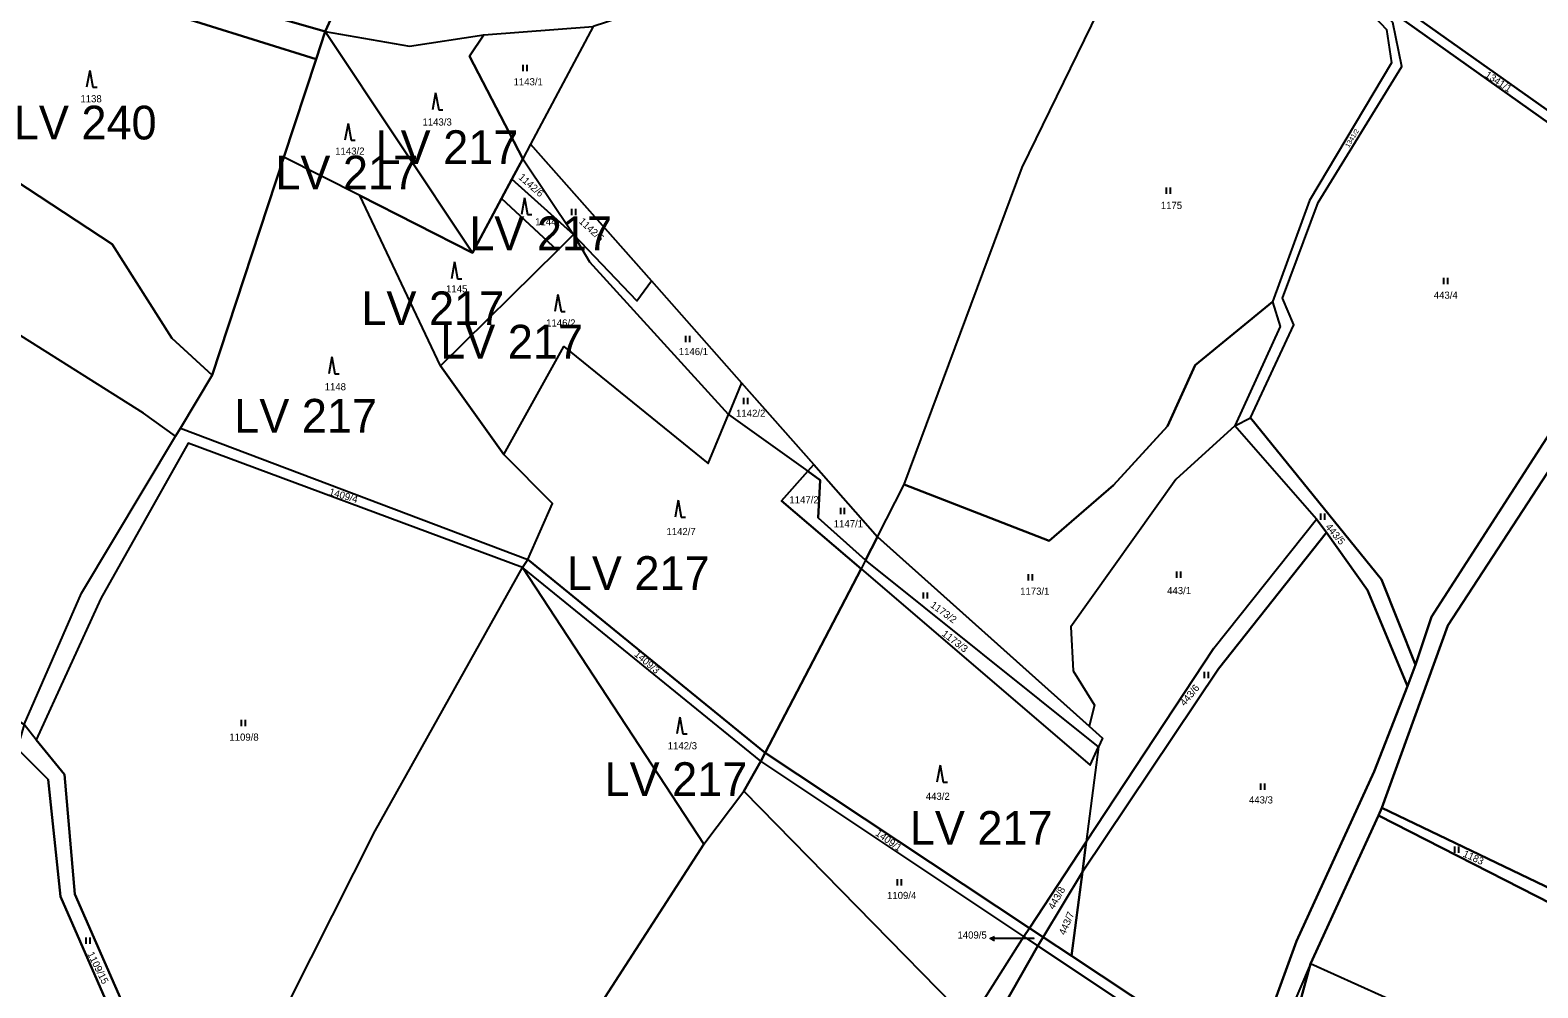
# Model space of a CAD drawing. Extents: x -588699 to -585793, y -1060280 to -1056731.
# Drawn here: x -587487.8 to -587129.7, y -1059020.2 to -1058792.9 of the extents above; entities that cross this region are included whole.
import ezdxf

# ---------------------------------------------------------------- set-up
doc = ezdxf.new("R2010")
doc.units = 0
for name, color, linetype in [('Druh pozemku', 7, 'Continuous'), ('Parcela nároku', 7, 'Continuous'), ('Parcelní číslo', 7, 'Continuous'), ('Vnější obvod_převzatý', 7, 'Continuous')]:
    doc.layers.add(name, color=color, linetype=linetype)

msp = doc.modelspace()

# ---------------------------------------------------------------- linework, layer by layer
at = {"layer": 'Druh pozemku'}
for p, q in [((-587473.6, -1058802.43), (-587474.33, -1058806.43)), ((-587473.6, -1058802.43), (-587472.87, -1058806.43)), ((-587370.75, -1058801.12), (-587370.75, -1058802.62)), ((-587369.72, -1058802.62), (-587369.72, -1058801.12)), ((-587472.87, -1058806.43), (-587471.87, -1058806.43)), ((-587391.46, -1058807.75), (-587392.2, -1058811.75)), ((-587391.46, -1058807.75), (-587390.73, -1058811.75)), ((-587390.73, -1058811.75), (-587389.73, -1058811.75)), ((-587412.26, -1058815), (-587412.99, -1058819)), ((-587412.26, -1058815), (-587411.53, -1058819)), ((-587411.53, -1058819), (-587410.53, -1058819)), ((-587218.02, -1058830.22), (-587218.02, -1058831.72)), ((-587216.99, -1058831.72), (-587216.99, -1058830.22)), ((-587370.36, -1058832.66), (-587371.09, -1058836.66)), ((-587370.36, -1058832.66), (-587369.63, -1058836.66)), ((-587359.2, -1058835.32), (-587359.2, -1058836.82)), ((-587358.18, -1058836.82), (-587358.18, -1058835.32)), ((-587369.63, -1058836.66), (-587368.63, -1058836.66)), ((-587386.97, -1058847.89), (-587387.7, -1058851.89)), ((-587386.97, -1058847.89), (-587386.24, -1058851.89)), ((-587386.24, -1058851.89), (-587385.24, -1058851.89)), ((-587152.12, -1058851.67), (-587152.12, -1058853.17)), ((-587151.09, -1058853.17), (-587151.09, -1058851.67)), ((-587362.41, -1058855.65), (-587363.15, -1058859.65)), ((-587362.41, -1058855.65), (-587361.68, -1058859.65)), ((-587361.68, -1058859.65), (-587360.68, -1058859.65)), ((-587332.14, -1058865.4), (-587332.14, -1058866.9)), ((-587331.11, -1058866.9), (-587331.11, -1058865.4)), ((-587416.11, -1058870.44), (-587416.84, -1058874.44)), ((-587416.11, -1058870.44), (-587415.38, -1058874.44)), ((-587415.38, -1058874.44), (-587414.38, -1058874.44)), ((-587318.39, -1058880.11), (-587318.39, -1058881.61)), ((-587317.36, -1058881.61), (-587317.36, -1058880.11)), ((-587333.88, -1058904.43), (-587334.61, -1058908.43)), ((-587333.88, -1058904.43), (-587333.15, -1058908.43)), ((-587295.35, -1058906.29), (-587295.35, -1058907.79)), ((-587294.33, -1058907.79), (-587294.33, -1058906.29)), ((-587333.15, -1058908.43), (-587332.15, -1058908.43)), ((-587181.3, -1058907.6), (-587181.3, -1058909.1)), ((-587180.28, -1058909.1), (-587180.28, -1058907.6)), ((-587250.74, -1058921.98), (-587250.74, -1058923.48)), ((-587249.71, -1058923.48), (-587249.71, -1058921.98)), ((-587215.49, -1058921.4), (-587215.49, -1058922.9)), ((-587214.46, -1058922.9), (-587214.46, -1058921.4)), ((-587275.66, -1058926.31), (-587275.66, -1058927.81)), ((-587274.64, -1058927.81), (-587274.64, -1058926.31)), ((-587208.94, -1058945.18), (-587208.94, -1058946.68)), ((-587207.92, -1058946.68), (-587207.92, -1058945.18)), ((-587437.66, -1058956.56), (-587437.66, -1058958.06)), ((-587436.64, -1058958.06), (-587436.64, -1058956.56)), ((-587333.48, -1058955.93), (-587334.21, -1058959.93)), ((-587333.48, -1058955.93), (-587332.75, -1058959.93)), ((-587332.75, -1058959.93), (-587331.75, -1058959.93)), ((-587271.67, -1058967.33), (-587272.41, -1058971.33)), ((-587271.67, -1058967.33), (-587270.94, -1058971.33)), ((-587270.94, -1058971.33), (-587269.94, -1058971.33)), ((-587195.58, -1058971.66), (-587195.58, -1058973.16)), ((-587194.56, -1058973.16), (-587194.56, -1058971.66)), ((-587149.51, -1058986.6), (-587149.51, -1058988.1)), ((-587148.48, -1058988.1), (-587148.48, -1058986.6)), ((-587281.85, -1058994.38), (-587281.85, -1058995.88)), ((-587280.83, -1058995.88), (-587280.83, -1058994.38)), ((-587474.54, -1059008.25), (-587474.54, -1059009.75)), ((-587473.52, -1059009.75), (-587473.52, -1059008.25))]:
    msp.add_line(p, q, dxfattribs=at)
at = {"layer": 'Parcela nároku'}
for points in [[(-587095.97, -1058834.07), (-587178.54, -1058775.59), (-587199.34, -1058768.09), (-587207.44, -1058733.83), (-587185.32, -1058687.57), (-587182.12, -1058689.03), (-587133.66, -1058696.26), (-587132.92, -1058684.88), (-587132.73, -1058682.03), (-587134.03, -1058665.11), (-587141.42, -1058647.46), (-587163.08, -1058643.05), (-587163.66, -1058639.96), (-587161.65, -1058627.33), (-587140.01, -1058634.05), (-587129.38, -1058630.44)], [(-587416.34, -1058790.27), (-587417.7, -1058793.2), (-587397.65, -1058796.7), (-587380.04, -1058794), (-587354.02, -1058791.99)], [(-587198.44, -1059040.46), (-587187.03, -1059009.07), (-587168.6, -1058968.87), (-587160.7, -1058948.56), (-587158.75, -1058943.55), (-587154.97, -1058932.12), (-587114.84, -1058869.89)], [(-587112.04, -1058874.39), (-587151.08, -1058934.21), (-587166.73, -1058977.44), (-587167.55, -1058979.24), (-587183.73, -1059014.5), (-587223.98, -1059108.89)]]:
    msp.add_lwpolyline(points, dxfattribs=at)
for points in [[(-587330.16, -1058779.5), (-587337.53, -1058786.61), (-587354.02, -1058791.99), (-587368.94, -1058819.94), (-587340.22, -1058852.41), (-587318.82, -1058876.59), (-587301.68, -1058895.97), (-587286.5, -1058913.13), (-587280.18, -1058900.72), (-587252.21, -1058825.49), (-587209.44, -1058737.86), (-587213.81, -1058720.6), (-587228.19, -1058686.62), (-587279.6, -1058678.24), (-587283.54, -1058683.14), (-587295.15, -1058721.3), (-587317.99, -1058756.82)], [(-587252.21, -1058825.49), (-587209.44, -1058737.86), (-587202.09, -1058770.02), (-587180.64, -1058776.9), (-587165.69, -1058792.7), (-587164.49, -1058800.66), (-587183.93, -1058833.32), (-587192.75, -1058857.34), (-587211.09, -1058872.41), (-587217.64, -1058886.83), (-587230.5, -1058900.89), (-587245.79, -1058914.12), (-587280.18, -1058900.72)], [(-587498.02, -1058773.26), (-587471.36, -1058772.88), (-587419.8, -1058789.18), (-587416.34, -1058790.27), (-587417.7, -1058793.2), (-587474.82, -1058776.74), (-587499.41, -1058777.39), (-587534.25, -1058785.03), (-587576.88, -1058810.62), (-587586.16, -1058816.34), (-587588.18, -1058814.68), (-587546.21, -1058786.56), (-587534.66, -1058781.41)], [(-587474.82, -1058776.74), (-587417.7, -1058793.2), (-587419.85, -1058799.73), (-587474.59, -1058782.55), (-587495.05, -1058781.41), (-587500.85, -1058781.64), (-587499.41, -1058777.39)], [(-587187.67, -1058862.81), (-587190.34, -1058856.52), (-587181.86, -1058833.77), (-587161.98, -1058801.53), (-587164.12, -1058791.02), (-587171.29, -1058783.54), (-587180.64, -1058776.9), (-587165.69, -1058792.7), (-587164.49, -1058800.66), (-587183.93, -1058833.32), (-587192.75, -1058857.34), (-587190.91, -1058863.2), (-587201.67, -1058886.81), (-587197.97, -1058884.91)], [(-587178.54, -1058775.59), (-587095.97, -1058834.07), (-587097.12, -1058836.2), (-587171.29, -1058783.54)], [(-587500.85, -1058781.64), (-587495.05, -1058781.41), (-587474.59, -1058782.55), (-587419.85, -1058799.73), (-587427.49, -1058822.99), (-587444.5, -1058874.75), (-587454.12, -1058865.97), (-587468.24, -1058843.69), (-587508.54, -1058817.27), (-587512.1, -1058815), (-587519.56, -1058810.2), (-587511.16, -1058782.05)], [(-587181.86, -1058833.77), (-587161.98, -1058801.53), (-587164.12, -1058791.02), (-587171.29, -1058783.54), (-587097.12, -1058836.2), (-587114.84, -1058869.89), (-587154.97, -1058932.12), (-587158.75, -1058943.55), (-587166.85, -1058923.26), (-587197.97, -1058884.91), (-587187.67, -1058862.81), (-587190.34, -1058856.52)], [(-587380.04, -1058794), (-587354.02, -1058791.99), (-587368.94, -1058819.94), (-587370.78, -1058823.39), (-587383.42, -1058799.04)], [(-587419.85, -1058799.73), (-587417.7, -1058793.2), (-587382.71, -1058845.74), (-587409.49, -1058832.13), (-587427.49, -1058822.99)], [(-587397.65, -1058796.7), (-587380.04, -1058794), (-587383.42, -1058799.04), (-587370.78, -1058823.39), (-587373.37, -1058828.25), (-587375.82, -1058832.84), (-587382.71, -1058845.74), (-587417.7, -1058793.2)], [(-587534.2, -1058801.97), (-587529.95, -1058803.18), (-587524.77, -1058814), (-587519.56, -1058810.2), (-587512.1, -1058815), (-587508.54, -1058817.27), (-587468.24, -1058843.69), (-587454.12, -1058865.97), (-587444.5, -1058874.75), (-587452.08, -1058887.38), (-587453.2, -1058889.25), (-587460.84, -1058883.78), (-587522.15, -1058845.16), (-587576.88, -1058810.62), (-587549.72, -1058797.54)], [(-587151.08, -1058934.21), (-587112.04, -1058874.39), (-587094.24, -1058884.94), (-587054.26, -1058810.56), (-587030.43, -1058823.41), (-587014.91, -1058836.17), (-587018.01, -1058859.21), (-587024.71, -1058873.71), (-587054.07, -1058916.3), (-587105.47, -1058969.38), (-587107.83, -1058978.95), (-587124.19, -1058997.85), (-587166.73, -1058977.44)], [(-587340.22, -1058852.41), (-587368.94, -1058819.94), (-587370.78, -1058823.39), (-587358.71, -1058841.41), (-587343.66, -1058857.1)], [(-587390.34, -1058872.54), (-587409.49, -1058832.13), (-587427.49, -1058822.99), (-587444.5, -1058874.75), (-587452.08, -1058887.38), (-587369.55, -1058918.49), (-587363.73, -1058905.23), (-587375.25, -1058893.58)], [(-587373.37, -1058828.25), (-587370.78, -1058823.39), (-587358.71, -1058841.41)], [(-587375.82, -1058832.84), (-587373.37, -1058828.25), (-587358.71, -1058841.41), (-587362.51, -1058845.15)], [(-587375.82, -1058832.84), (-587362.51, -1058845.15), (-587390.34, -1058872.54), (-587409.49, -1058832.13), (-587382.71, -1058845.74)], [(-587354.84, -1058847.98), (-587358.71, -1058841.41), (-587362.51, -1058845.15), (-587390.34, -1058872.54), (-587375.25, -1058893.58), (-587361, -1058867.92), (-587326.78, -1058895.73), (-587321.93, -1058884.06)], [(-587358.71, -1058841.41), (-587343.66, -1058857.1), (-587340.22, -1058852.41), (-587318.82, -1058876.59), (-587321.93, -1058884.06), (-587354.84, -1058847.98)], [(-587522.15, -1058845.16), (-587543.94, -1058911.31), (-587530.26, -1058930.8), (-587489.18, -1058957.68), (-587475.53, -1058926.48), (-587453.2, -1058889.25), (-587460.84, -1058883.78)], [(-587240.62, -1058934.52), (-587240.05, -1058944.97), (-587235.03, -1058953.09), (-587236.26, -1058958.05), (-587286.5, -1058913.13), (-587280.18, -1058900.72), (-587245.79, -1058914.12), (-587230.5, -1058900.89), (-587217.64, -1058886.83), (-587211.09, -1058872.41), (-587192.75, -1058857.34), (-587190.91, -1058863.2), (-587201.67, -1058886.81), (-587215.69, -1058899.54)], [(-587326.78, -1058895.73), (-587321.93, -1058884.06), (-587303.11, -1058897.58), (-587309.31, -1058904.57), (-587290.42, -1058920.75), (-587313.22, -1058964.38), (-587369.55, -1058918.49), (-587363.73, -1058905.23), (-587375.25, -1058893.58), (-587361, -1058867.92)], [(-587301.68, -1058895.97), (-587318.82, -1058876.59), (-587321.93, -1058884.06), (-587303.11, -1058897.58)], [(-587197.97, -1058884.91), (-587166.85, -1058923.26), (-587158.75, -1058943.55), (-587160.7, -1058948.56), (-587170.21, -1058925.83), (-587179.94, -1058912.09), (-587182.28, -1058908.96), (-587201.67, -1058886.81)], [(-587489.18, -1058957.68), (-587475.53, -1058926.48), (-587453.2, -1058889.25), (-587452.08, -1058887.38), (-587369.55, -1058918.49), (-587370.84, -1058920.39), (-587450.19, -1058890.89), (-587470.98, -1058927.74), (-587486.32, -1058961.34)], [(-587201.67, -1058886.81), (-587215.69, -1058899.54), (-587240.62, -1058934.52), (-587240.05, -1058944.97), (-587235.03, -1058953.09), (-587236.26, -1058958.05), (-587233.09, -1058960.89), (-587234.03, -1058962.97), (-587236.95, -1058985.52), (-587206.63, -1058939.58), (-587182.28, -1058908.96)], [(-587470.98, -1058927.74), (-587486.32, -1058961.34), (-587479.58, -1058969.58), (-587477.12, -1058997.98), (-587465.03, -1059025.53), (-587462.84, -1059036.38), (-587445.39, -1059076.03), (-587426.09, -1059023.1), (-587405.83, -1058982.93), (-587370.84, -1058920.39), (-587450.19, -1058890.89)], [(-587303.11, -1058897.58), (-587301.68, -1058895.97), (-587286.5, -1058913.13), (-587289.35, -1058918.66), (-587300.64, -1058908.61), (-587300.16, -1058899.7)], [(-587309.31, -1058904.57), (-587303.11, -1058897.58), (-587300.16, -1058899.7), (-587300.64, -1058908.61), (-587289.35, -1058918.66), (-587290.42, -1058920.75)], [(-587206.63, -1058939.58), (-587182.28, -1058908.96), (-587179.94, -1058912.09), (-587205.52, -1058944.5), (-587237.88, -1058992.68), (-587236.95, -1058985.52)], [(-587289.35, -1058918.66), (-587286.5, -1058913.13), (-587236.26, -1058958.05), (-587233.09, -1058960.89), (-587234.03, -1058962.97)], [(-587205.52, -1058944.5), (-587179.94, -1058912.09), (-587170.21, -1058925.83), (-587160.7, -1058948.56), (-587168.6, -1058968.87), (-587187.03, -1059009.07), (-587198.44, -1059040.46), (-587240.46, -1059012.61), (-587237.88, -1058992.68)], [(-587472.64, -1059160.39), (-587420.19, -1059028.43), (-587426.09, -1059023.1), (-587405.83, -1058982.93), (-587370.84, -1058920.39), (-587327.75, -1058986.1), (-587352, -1059023.57), (-587374.2, -1059062.49), (-587384.36, -1059094.45), (-587392.6, -1059142.78), (-587403.28, -1059136.63), (-587416.21, -1059132.26), (-587431.57, -1059132.26), (-587446.44, -1059137.12), (-587462.61, -1059149.09)], [(-587370.84, -1058920.39), (-587369.55, -1058918.49), (-587313.22, -1058964.38), (-587314.26, -1058966.37)], [(-587314.26, -1058966.37), (-587370.84, -1058920.39), (-587327.75, -1058986.1), (-587318.3, -1058973.51)], [(-587313.22, -1058964.38), (-587290.42, -1058920.75), (-587236, -1058967.34), (-587234.03, -1058962.97), (-587236.95, -1058985.52), (-587250.46, -1059005.98)], [(-587234.03, -1058962.97), (-587289.35, -1058918.66), (-587290.42, -1058920.75), (-587236, -1058967.34)], [(-587479.58, -1058969.58), (-587486.32, -1058961.34), (-587489.18, -1058957.68), (-587490.84, -1058963.37), (-587483.48, -1058970.73), (-587480.52, -1058998.52), (-587467.05, -1059029.25), (-587466.55, -1059035.93), (-587447.41, -1059081.29), (-587445.39, -1059076.03), (-587462.84, -1059036.38), (-587465.03, -1059025.53), (-587477.12, -1058997.98)], [(-587507.67, -1059010.75), (-587518.99, -1059041.82), (-587509.34, -1059046.17), (-587512.35, -1059055.56), (-587522.91, -1059052.02), (-587539.49, -1059095.18), (-587562.32, -1059174.45), (-587544.58, -1059180.95), (-587489.61, -1059179.49), (-587482.72, -1059171.73), (-587447.41, -1059081.29), (-587466.55, -1059035.93), (-587467.05, -1059029.25), (-587480.52, -1058998.52), (-587483.48, -1058970.73), (-587490.84, -1058963.37)], [(-587314.26, -1058966.37), (-587318.3, -1058973.51), (-587264.6, -1059028.24), (-587251.79, -1059007.99)], [(-587313.22, -1058964.38), (-587250.46, -1059005.98), (-587251.79, -1059007.99), (-587314.26, -1058966.37)], [(-587352, -1059023.57), (-587327.75, -1058986.1), (-587318.3, -1058973.51), (-587264.6, -1059028.24), (-587323.79, -1059134.74), (-587339.95, -1059180.25), (-587392.6, -1059142.78), (-587384.36, -1059094.45), (-587374.2, -1059062.49)], [(-587167.55, -1058979.24), (-587166.73, -1058977.44), (-587124.19, -1058997.85), (-587126.31, -1059000.3)], [(-587178.21, -1059042.85), (-587173.18, -1059040.84), (-587161.23, -1059024.64), (-587183.73, -1059014.5), (-587167.55, -1058979.24), (-587126.31, -1059000.3), (-587104.24, -1059012.16), (-587128.43, -1059090.29), (-587155.26, -1059188.4), (-587209.63, -1059156.73), (-587230.3, -1059139), (-587220.32, -1059110.26), (-587212, -1059090.39), (-587190.48, -1059039.37)], [(-587250.46, -1059005.98), (-587236.95, -1058985.52), (-587237.88, -1058992.68), (-587247.23, -1059008.12)], [(-587247.23, -1059008.12), (-587237.88, -1058992.68), (-587240.46, -1059012.61)], [(-587251.79, -1059007.99), (-587250.46, -1059005.98), (-587247.23, -1059008.12), (-587248.47, -1059010.2)], [(-587339.95, -1059180.25), (-587323.79, -1059134.74), (-587264.6, -1059028.24), (-587251.79, -1059007.99), (-587248.47, -1059010.2), (-587300.25, -1059101.27), (-587302.6, -1059105.17), (-587320.05, -1059135.74), (-587337.12, -1059182.26)], [(-587248.47, -1059010.2), (-587199.45, -1059042.86), (-587227.19, -1059109.85), (-587235.69, -1059139.11), (-587239.06, -1059150.72), (-587300.25, -1059101.27)], [(-587248.47, -1059010.2), (-587247.23, -1059008.12), (-587240.46, -1059012.61), (-587198.44, -1059040.46), (-587199.45, -1059042.86)], [(-587223.98, -1059108.89), (-587232.05, -1059137.8), (-587230.3, -1059139), (-587220.32, -1059110.26), (-587212, -1059090.39), (-587190.48, -1059039.37), (-587183.73, -1059014.5)], [(-587161.23, -1059024.64), (-587183.73, -1059014.5), (-587190.48, -1059039.37), (-587178.21, -1059042.85), (-587173.18, -1059040.84)]]:
    msp.add_lwpolyline(points, close=True, dxfattribs=at)
at = {"layer": 'Parcelní číslo'}
for p, q in [((-587256.75, -1059008.49), (-587259.75, -1059008.49)), ((-587249.31, -1059008.49), (-587256.75, -1059008.49))]:
    msp.add_line(p, q, dxfattribs=at)
msp.add_lwpolyline([(-587258.75, -1059008.99), (-587259.75, -1059008.49), (-587258.75, -1059007.99)], dxfattribs=at)
at = {"layer": 'Vnější obvod_převzatý'}
msp.add_lwpolyline([(-587452.08, -1058887.38), (-587444.5, -1058874.75), (-587427.49, -1058822.99), (-587419.85, -1058799.73), (-587417.7, -1058793.2), (-587416.34, -1058790.27), (-587393.05, -1058739.96)], dxfattribs=at)

# ---------------------------------------------------------------- texts
at = {"layer": 'Parcela nároku'}
for s, height, rotation, p in [('1341/1', 1.7, 326.3099, (-587142.43, -1058803.87)), ('1341/2', 1.14, 58.9585, (-587174.59, -1058820.85)), ('1142/6', 1.7, 318.5261, (-587371.92, -1058828.01)), ('1142/5', 1.7, 317.2204, (-587357.58, -1058838.46)), ('1409/4', 1.7, 343.715, (-587416.9, -1058903.17)), ('443/5', 1.7, 310.0429, (-587180.28, -1058910.85)), ('1173/2', 1.7, 323.9035, (-587274.13, -1058929.66)), ('1173/3', 1.7, 322.1918, (-587271.4, -1058936.44)), ('1409/3', 1.7, 319.4345, (-587344.43, -1058941.25)), ('443/6', 1.7, 50.3483, (-587213.57, -1058953.43)), ('1409/1', 1.7, 324.4441, (-587287.19, -1058983.84)), ('1183', 1.7, 335.3084, (-587147.66, -1058988.96)), ('443/8', 1.7, 60.3762, (-587244.67, -1059001.74)), ('443/7', 1.7, 66.8384, (-587242, -1059007.81)), ('1109/15', 1.7, 296.4603, (-587474.22, -1059012.11))]:
    msp.add_text(s, height=height, rotation=rotation, dxfattribs=at).set_placement(p)
for s, height, p in [('1143/1', 1.7, (-587372.95, -1058805.97)), ('1138', 1.7, (-587475.81, -1058810)), ('1143/3', 1.7, (-587394.58, -1058815.52)), ('1143/2', 1.7, (-587415.3, -1058822.43)), ('1175', 1.7, (-587219.26, -1058835.31)), ('1144', 1.7, (-587367.83, -1058839.2)), ('1145', 1.7, (-587388.98, -1058855.11)), ('443/4', 1.7, (-587154.43, -1058856.62)), ('1146/2', 1.7, (-587365.21, -1058863.22)), ('1146/1', 1.7, (-587333.72, -1058870)), ('1148', 1.7, (-587417.81, -1058878.36)), ('1142/2', 1.7, (-587320.12, -1058884.65)), ('1147/2', 1.7, (-587307.45, -1058905.19)), ('1147/1', 1.7, (-587296.92, -1058910.87)), ('1142/7', 1.7, (-587336.65, -1058912.72)), ('1173/1', 1.7, (-587252.66, -1058926.88)), ('443/1', 1.7, (-587217.75, -1058926.74)), ('1109/8', 1.7, (-587440.44, -1058961.52)), ('1142/3', 1.7, (-587336.34, -1058963.57)), ('443/2', 1.7, (-587275.06, -1058975.56)), ('443/3', 1.7, (-587198.32, -1058976.42)), ('1109/4', 1.7, (-587284.27, -1058999.1)), ('1409/5', 0.1, (-587249.51, -1059008.49))]:
    msp.add_text(s, height=height, dxfattribs=at).set_placement(p)
at = {"layer": 'Parcelní číslo'}
msp.add_text('1409/5', height=1.7, dxfattribs=at).set_placement((-587267.54, -1059008.49))
at = {"layer": 'Vnější obvod_převzatý'}
for s, p in [('LV 240', (-587491.63, -1058818.81)), ('LV 217', (-587405.72, -1058824.64)), ('LV 217', (-587429.53, -1058830.66)), ('LV 217', (-587383.47, -1058845.1)), ('LV 217', (-587409.1, -1058862.89)), ('LV 217', (-587390.38, -1058870.81)), ('LV 217', (-587439.28, -1058888.4)), ('LV 217', (-587360.31, -1058925.73)), ('LV 217', (-587351.35, -1058974.64)), ('LV 217', (-587278.86, -1058986.22))]:
    msp.add_text(s, height=8, dxfattribs=at).set_placement(p)

doc.saveas('drawing.dxf')
